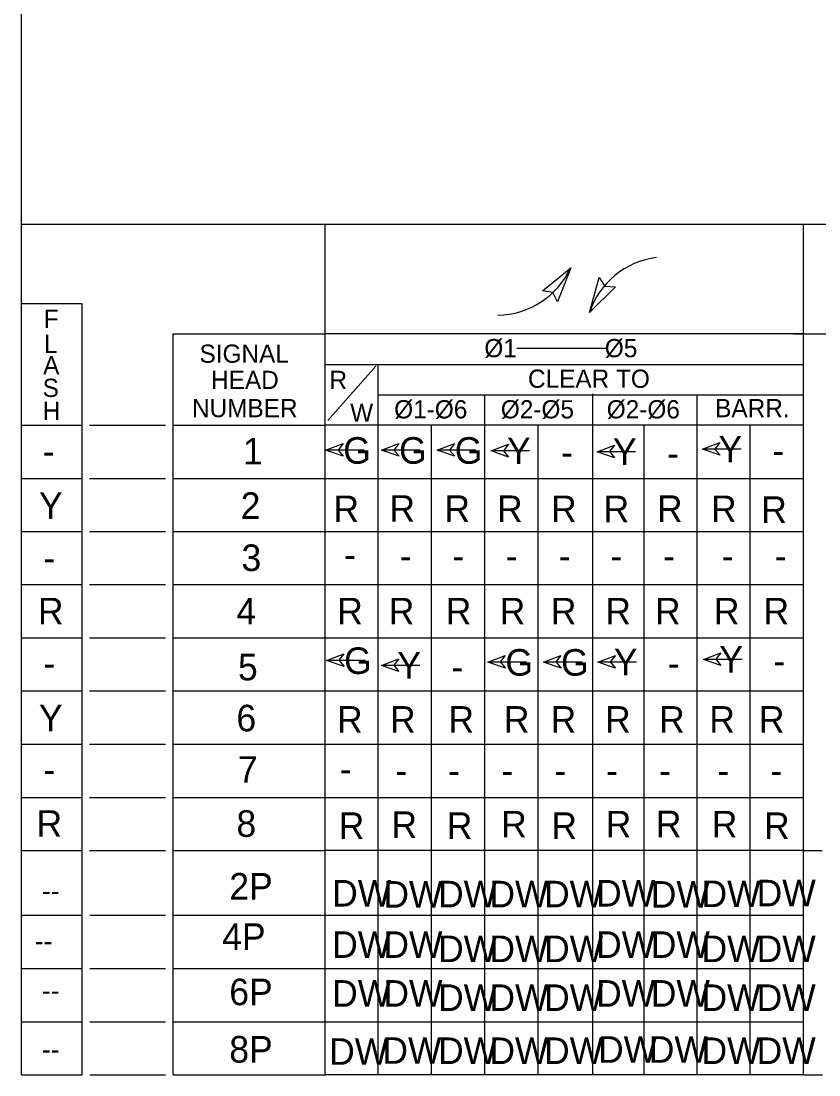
# Model space of a CAD drawing. Extents: x 0 to 3.01, y -0.05 to 1.83.
# Drawn here: x 2.2984 to 2.5103, y 1.2756 to 1.5553 of the extents above; entities that cross this region are included whole.
import ezdxf

# ---------------------------------------------------------------- set-up
doc = ezdxf.new("R2010")
doc.units = 0
for name, color, linetype in [('TR_TS_Border', 7, 'Continuous'), ('TR_TS_Phase1', 7, 'Continuous'), ('TR_TS_Phase2', 7, 'Continuous'), ('TR_TS_Phase3', 7, 'Continuous'), ('TR_TS_Phase4', 7, 'Continuous'), ('TR_TS_Phase5', 7, 'Continuous'), ('TR_TS_Phase6', 7, 'Continuous'), ('TR_TS_Phase7', 7, 'Continuous'), ('TR_TS_Phase8', 7, 'Continuous')]:
    doc.layers.add(name, color=color, linetype=linetype)

msp = doc.modelspace()

# ---------------------------------------------------------------- linework, layer by layer
at = {"layer": 'TR_TS_Border'}
for p, q in [((2.2983738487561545, 1.7049511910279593), (2.2983738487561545, 1.27559374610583)), ((2.907476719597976, 1.5013454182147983), (2.2983738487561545, 1.5013454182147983)), ((2.3790461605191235, 1.5013453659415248), (2.3790461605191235, 1.275593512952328)), ((2.506118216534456, 1.5013455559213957), (2.506118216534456, 1.27559374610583)), ((2.2983738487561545, 1.4803417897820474), (2.314508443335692, 1.4803417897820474)), ((2.314508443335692, 1.4803417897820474), (2.314508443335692, 1.27559374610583)), ((2.338710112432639, 1.4722744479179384), (2.379046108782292, 1.4722744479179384)), ((2.338710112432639, 1.4722744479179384), (2.338710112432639, 1.27559374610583)), ((2.506118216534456, 1.4722744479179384), (2.379046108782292, 1.4722744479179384)), ((2.503587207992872, 1.4722744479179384), (2.5267743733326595, 1.4722744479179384)), ((2.4300997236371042, 1.468530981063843), (2.453723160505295, 1.468530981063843)), ((2.379046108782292, 1.4642071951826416), (2.506118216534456, 1.4642071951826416)), ((2.379889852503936, 1.4492854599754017), (2.392597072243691, 1.4637328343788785)), ((2.393177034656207, 1.4642071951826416), (2.393177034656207, 1.27559374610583)), ((2.393177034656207, 1.4561402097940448), (2.506118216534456, 1.4561402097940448)), ((2.421464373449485, 1.4561402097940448), (2.421464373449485, 1.27559374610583)), ((2.450123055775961, 1.4564049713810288), (2.450123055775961, 1.275858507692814)), ((2.4779094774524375, 1.4561402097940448), (2.4779094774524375, 1.27559374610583)), ((2.2983738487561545, 1.4480727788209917), (2.314508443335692, 1.4480727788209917)), ((2.316564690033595, 1.4480727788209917), (2.3367063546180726, 1.4480727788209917)), ((2.338710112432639, 1.4480727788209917), (2.379046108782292, 1.4480727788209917)), ((2.506118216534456, 1.4480727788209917), (2.379046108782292, 1.4480727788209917)), ((2.4073335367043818, 1.4480727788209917), (2.4073335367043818, 1.27559374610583)), ((2.4355952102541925, 1.4480727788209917), (2.4355952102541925, 1.27559374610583)), ((2.4637786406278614, 1.4480727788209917), (2.4637786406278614, 1.27559374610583)), ((2.491987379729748, 1.4480727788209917), (2.491987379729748, 1.27559374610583)), ((2.2983738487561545, 1.433941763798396), (2.314508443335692, 1.433941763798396)), ((2.316564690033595, 1.433941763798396), (2.3367063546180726, 1.433941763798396)), ((2.338710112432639, 1.433941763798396), (2.506118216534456, 1.433941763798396)), ((2.2983738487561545, 1.4198639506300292), (2.314508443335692, 1.4198639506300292)), ((2.316564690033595, 1.4198639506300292), (2.3367063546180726, 1.4198639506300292)), ((2.338710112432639, 1.4198639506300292), (2.506118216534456, 1.4198639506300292)), ((2.2983738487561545, 1.405733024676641), (2.314508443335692, 1.405733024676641)), ((2.316564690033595, 1.405733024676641), (2.3367063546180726, 1.405733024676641)), ((2.338710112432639, 1.405733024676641), (2.506118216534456, 1.405733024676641)), ((2.2983738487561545, 1.3916020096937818), (2.314508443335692, 1.3916020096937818)), ((2.316564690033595, 1.3916020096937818), (2.3367063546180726, 1.3916020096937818)), ((2.338710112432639, 1.3916020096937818), (2.506118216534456, 1.3916020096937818)), ((2.2983738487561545, 1.3775241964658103), (2.314508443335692, 1.3775241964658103)), ((2.316564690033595, 1.3775241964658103), (2.3367063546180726, 1.3775241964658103)), ((2.338710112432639, 1.3775241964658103), (2.506118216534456, 1.3775241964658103)), ((2.2983738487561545, 1.3633932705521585), (2.314508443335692, 1.3633932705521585)), ((2.316564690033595, 1.3633932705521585), (2.3367063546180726, 1.3633932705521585)), ((2.338710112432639, 1.3633932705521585), (2.506118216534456, 1.3633932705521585)), ((2.2983738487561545, 1.3492622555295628), (2.314508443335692, 1.3492622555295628)), ((2.316564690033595, 1.3492622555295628), (2.3367063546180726, 1.3492622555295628)), ((2.338710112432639, 1.3492622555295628), (2.506118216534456, 1.3492622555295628)), ((2.2983738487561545, 1.3351314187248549), (2.314508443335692, 1.3351314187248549)), ((2.316564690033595, 1.3351314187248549), (2.3367063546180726, 1.3351314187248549)), ((2.338710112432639, 1.3351314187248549), (2.379046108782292, 1.3351314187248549)), ((2.506118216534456, 1.3351314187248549), (2.379046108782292, 1.3351314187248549)), ((2.506118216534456, 1.3351314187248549), (2.5111802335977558, 1.3351314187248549)), ((2.298447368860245, 1.3179863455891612), (2.314581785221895, 1.3179863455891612)), ((2.3166380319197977, 1.3179863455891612), (2.336779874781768, 1.3179863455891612)), ((2.3387833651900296, 1.3179863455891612), (2.5061917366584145, 1.3179863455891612)), ((2.298447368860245, 1.3038554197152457), (2.314581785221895, 1.3038554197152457)), ((2.3166380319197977, 1.3038554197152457), (2.336779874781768, 1.3038554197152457)), ((2.3387833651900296, 1.3038554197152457), (2.5061917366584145, 1.3038554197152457)), ((2.298447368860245, 1.2897245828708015), (2.314581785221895, 1.2897245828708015)), ((2.3166380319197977, 1.2897245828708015), (2.336779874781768, 1.2897245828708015)), ((2.3387833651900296, 1.2897245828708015), (2.5061917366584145, 1.2897245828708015)), ((2.298447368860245, 1.27559374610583), (2.314581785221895, 1.27559374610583)), ((2.3166380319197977, 1.27559374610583), (2.336779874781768, 1.27559374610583)), ((2.3387833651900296, 1.27559374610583), (2.3791196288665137, 1.27559374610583)), ((2.5061917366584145, 1.27559374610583), (2.3791196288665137, 1.27559374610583)), ((2.5061917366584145, 1.27559374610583), (2.5112536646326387, 1.27559374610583))]:
    msp.add_line(p, q, dxfattribs=at)
at = {"layer": 'TR_TS_Phase1'}
for p, q in [((2.4368316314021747, 1.4837736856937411), (2.4443714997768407, 1.4898253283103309)), ((2.4443714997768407, 1.4898253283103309), (2.440849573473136, 1.480800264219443)), ((2.4396055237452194, 1.483325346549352), (2.4368316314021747, 1.4837736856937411)), ((2.440849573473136, 1.480800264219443), (2.4396055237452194, 1.483325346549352)), ((2.3792738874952, 1.4414179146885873), (2.383908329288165, 1.443180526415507)), ((2.3895352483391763, 1.4414179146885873), (2.3792738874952, 1.4414179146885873)), ((2.383952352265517, 1.439809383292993), (2.3792738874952, 1.4414179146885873)), ((2.383908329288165, 1.443180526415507), (2.3825789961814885, 1.441476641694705)), ((2.3825789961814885, 1.441476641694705), (2.383952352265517, 1.439809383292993)), ((2.3941049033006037, 1.4414179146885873), (2.3987393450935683, 1.443180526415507)), ((2.4043663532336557, 1.4414179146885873), (2.3941049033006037, 1.4414179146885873)), ((2.398783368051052, 1.439809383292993), (2.3941049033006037, 1.4414179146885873)), ((2.3987393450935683, 1.443180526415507), (2.397410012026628, 1.441476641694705)), ((2.397410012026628, 1.441476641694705), (2.398783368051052, 1.439809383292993)), ((2.4088982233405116, 1.4414179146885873), (2.4135327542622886, 1.443180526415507)), ((2.419159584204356, 1.4414179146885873), (2.4088982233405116, 1.4414179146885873)), ((2.4135767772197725, 1.439809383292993), (2.4088982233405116, 1.4414179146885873)), ((2.4135327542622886, 1.443180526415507), (2.4122033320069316, 1.441476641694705)), ((2.4122033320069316, 1.441476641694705), (2.4135767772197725, 1.439809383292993)), ((2.4232023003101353, 1.4412230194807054), (2.42783665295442, 1.4429858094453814)), ((2.4334633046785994, 1.4412230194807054), (2.4232023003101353, 1.4412230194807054)), ((2.42788067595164, 1.4396146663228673), (2.4232023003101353, 1.4412230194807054)), ((2.42783665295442, 1.4429858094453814), (2.4265074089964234, 1.4412817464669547)), ((2.4265074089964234, 1.4412817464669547), (2.42788067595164, 1.4396146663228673)), ((2.451358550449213, 1.4409954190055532), (2.4559929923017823, 1.442758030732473)), ((2.4616196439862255, 1.4409954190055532), (2.451358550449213, 1.4409954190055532)), ((2.45603701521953, 1.439386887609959), (2.451358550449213, 1.4409954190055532)), ((2.4559929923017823, 1.442758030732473), (2.4546636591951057, 1.4410542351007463)), ((2.4546636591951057, 1.4410542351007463), (2.45603701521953, 1.439386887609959)), ((2.4793790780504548, 1.441678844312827), (2.4840134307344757, 1.443441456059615)), ((2.4896400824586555, 1.441678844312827), (2.4793790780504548, 1.441678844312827)), ((2.4840574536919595, 1.4400703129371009), (2.4793790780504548, 1.441678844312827)), ((2.4840134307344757, 1.443441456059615), (2.482684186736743, 1.441737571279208)), ((2.482684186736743, 1.441737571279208), (2.4840574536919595, 1.4400703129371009))]:
    msp.add_line(p, q, dxfattribs=at)
msp.add_arc((2.4246866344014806, 1.4988934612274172), 0.02161745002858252, 270.9422666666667, 335.3874333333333, dxfattribs=at)
at = {"layer": 'TR_TS_Phase5'}
for p, q in [((2.4493976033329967, 1.4779521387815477), (2.4519162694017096, 1.4873070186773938)), ((2.4519162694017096, 1.4873070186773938), (2.4534273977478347, 1.4849325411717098)), ((2.4562339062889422, 1.4847884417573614), (2.4493976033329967, 1.4779521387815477)), ((2.4534273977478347, 1.4849325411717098), (2.4562339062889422, 1.4847884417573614)), ((2.4796064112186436, 1.3858729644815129), (2.48424085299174, 1.387635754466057)), ((2.48424085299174, 1.387635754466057), (2.4829115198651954, 1.3859316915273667)), ((2.3795012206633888, 1.3856120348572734), (2.384135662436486, 1.3873748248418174)), ((2.3897626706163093, 1.3856120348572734), (2.3795012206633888, 1.3856120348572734)), ((2.384179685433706, 1.3840036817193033), (2.3795012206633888, 1.3856120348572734)), ((2.384135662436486, 1.3873748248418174), (2.3828063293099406, 1.3856707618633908)), ((2.3828063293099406, 1.3856707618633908), (2.384179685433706, 1.3840036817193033)), ((2.3940705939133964, 1.3842786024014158), (2.3987050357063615, 1.3860412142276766)), ((2.3987050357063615, 1.3860412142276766), (2.3973757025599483, 1.3843374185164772)), ((2.4223260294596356, 1.3851563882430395), (2.426960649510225, 1.386919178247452)), ((2.4325874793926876, 1.3851563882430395), (2.4223260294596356, 1.3851563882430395)), ((2.427004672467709, 1.3835478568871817), (2.4223260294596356, 1.3851563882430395)), ((2.426960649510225, 1.386919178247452), (2.4256311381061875, 1.3852151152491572)), ((2.4256311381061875, 1.3852151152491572), (2.427004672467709, 1.3835478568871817)), ((2.437119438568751, 1.3851563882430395), (2.4417540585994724, 1.386919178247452)), ((2.4473808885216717, 1.3851563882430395), (2.437119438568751, 1.3851563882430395)), ((2.441798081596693, 1.3835478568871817), (2.437119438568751, 1.3851563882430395)), ((2.4417540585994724, 1.386919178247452), (2.440424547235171, 1.3852151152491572)), ((2.440424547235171, 1.3852151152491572), (2.441798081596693, 1.3835478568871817)), ((2.4515859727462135, 1.385189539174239), (2.4562204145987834, 1.3869523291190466)), ((2.461847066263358, 1.385189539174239), (2.4515859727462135, 1.385189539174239)), ((2.4562644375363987, 1.3835810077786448), (2.4515859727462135, 1.385189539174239)), ((2.4562204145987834, 1.3869523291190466), (2.4548910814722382, 1.3852483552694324)), ((2.4548910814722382, 1.3852483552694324), (2.4562644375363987, 1.3835810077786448)), ((2.489867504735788, 1.3858729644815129), (2.4796064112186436, 1.3858729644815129)), ((2.4842848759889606, 1.3842644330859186), (2.4796064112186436, 1.3858729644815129)), ((2.4829115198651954, 1.3859316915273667), (2.4842848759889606, 1.3842644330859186)), ((2.4043316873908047, 1.3842786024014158), (2.3940705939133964, 1.3842786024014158)), ((2.3987490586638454, 1.382670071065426), (2.3940705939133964, 1.3842786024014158)), ((2.3973757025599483, 1.3843374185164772), (2.3987490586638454, 1.382670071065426))]:
    msp.add_line(p, q, dxfattribs=at)
msp.add_arc((2.4698457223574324, 1.4711175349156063), 0.021617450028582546, 97.19140000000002, 161.63656666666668, dxfattribs=at)

# ---------------------------------------------------------------- texts
at = {"layer": 'TR_TS_Border'}
for s, height, p in [('F', 0.004840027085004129, (2.304359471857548, 1.473908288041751)), ('L', 0.004840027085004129, (2.3044841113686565, 1.4672645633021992)), ('SIGNAL', 0.004840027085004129, (2.345774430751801, 1.464628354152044)), ('Ø1             Ø5', 0.004840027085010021, (2.4214208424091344, 1.466104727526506)), ('A', 0.004840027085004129, (2.30423977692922, 1.46157000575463)), ('S', 0.004840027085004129, (2.3040989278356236, 1.4555591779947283)), ('HEAD', 0.004840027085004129, (2.34884864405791, 1.457668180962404)), ('R', 0.004840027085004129, (2.38029688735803, 1.457668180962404)), ('CLEAR TO', 0.004840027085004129, (2.4330146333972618, 1.4579846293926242)), ('NUMBER', 0.004840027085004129, (2.3437718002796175, 1.4501810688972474)), ('Ø1-Ø6', 0.004840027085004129, (2.397485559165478, 1.4498646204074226)), ('Ø2-Ø5', 0.004840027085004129, (2.4258108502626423, 1.4498646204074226)), ('Ø2-Ø6', 0.004840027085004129, (2.4539413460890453, 1.4498646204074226)), ('BARR.', 0.004840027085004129, (2.4827323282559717, 1.4501810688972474)), ('H', 0.004840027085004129, (2.304124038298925, 1.4494428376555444)), ('W', 0.004840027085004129, (2.3857909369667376, 1.4489682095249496))]:
    msp.add_text(s, height=height, rotation=360, dxfattribs=at).set_placement(p)
at = {"layer": 'TR_TS_Phase1'}
for s, p in [('1', (2.357327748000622, 1.4376521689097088)), ('G', (2.383950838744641, 1.4378358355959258)), ('G', (2.3987823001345, 1.4378358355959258)), ('G', (2.4135757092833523, 1.4378358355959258)), ('Y', (2.427431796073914, 1.4377340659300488)), ('Y', (2.455588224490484, 1.4375065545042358)), ('Y', (2.483608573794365, 1.4381895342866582)), ('-', (2.304098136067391, 1.4376521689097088)), ('-', (2.4979788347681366, 1.4378358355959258)), ('-', (2.441802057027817, 1.4373803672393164)), ('-', (2.469958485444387, 1.4371528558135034))]:
    msp.add_text(s, height=0.007050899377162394, dxfattribs=at).set_placement(p)
at = {"layer": 'TR_TS_Phase2'}
for s, p in [('Y', (2.3031285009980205, 1.4231914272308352)), ('2', (2.3567041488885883, 1.4231914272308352))]:
    msp.add_text(s, height=0.007050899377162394, rotation=360, dxfattribs=at).set_placement(p)
for s, height, p in [('R', 0.007050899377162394, (2.381339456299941, 1.4223307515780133)), ('R', 0.007050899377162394, (2.3962089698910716, 1.4224151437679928)), ('R', 0.007050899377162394, (2.4108127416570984, 1.422395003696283)), ('R', 0.007050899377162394, (2.424800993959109, 1.4223560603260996)), ('R', 0.007050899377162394, (2.4391517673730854, 1.4223357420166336)), ('R', 0.007050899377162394, (2.4530972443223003, 1.4223218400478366)), ('R', 0.007050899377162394, (2.4672795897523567, 1.4223858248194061)), ('R', 0.007050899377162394, (2.481631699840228, 1.4223307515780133)), ('R', 0.007050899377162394, (2.4949716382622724, 1.4221420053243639)), ('2P', 0.007050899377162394, (2.3536810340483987, 1.3221382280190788)), ('DW', 0.007050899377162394, (2.3809983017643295, 1.3202967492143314)), ('DW', 0.007050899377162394, (2.394601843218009, 1.319995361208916)), ('DW', 0.007050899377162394, (2.409129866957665, 1.3200736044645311)), ('DW', 0.007050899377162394, (2.4227592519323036, 1.3200736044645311)), ('DW', 0.007050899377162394, (2.4372873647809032, 1.3200736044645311)), ('DW', 0.007050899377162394, (2.45109845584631, 1.3202967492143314)), ('DW', 0.007050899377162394, (2.4656265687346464, 1.319995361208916)), ('DW', 0.007050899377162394, (2.47910009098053, 1.320149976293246)), ('DW', 0.007050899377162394, (2.493741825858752, 1.3203438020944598)), ('--', 0.005251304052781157, (2.303913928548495, 1.321869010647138))]:
    msp.add_text(s, height=height, dxfattribs=at).set_placement(p)
at = {"layer": 'TR_TS_Phase3'}
for s, p in [('3', (2.356925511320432, 1.4093552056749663)), ('-', (2.384202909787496, 1.4102400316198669)), ('-', (2.39892440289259, 1.4098391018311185)), ('-', (2.4129585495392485, 1.4098391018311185)), ('-', (2.4271453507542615, 1.4098391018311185)), ('-', (2.441179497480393, 1.4098391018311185)), ('-', (2.4549020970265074, 1.4098391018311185)), ('-', (2.468936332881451, 1.4098391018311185)), ('-', (2.4845156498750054, 1.4098391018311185)), ('-', (2.498549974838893, 1.4098391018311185)), ('-', (2.304339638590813, 1.4093552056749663))]:
    msp.add_text(s, height=0.007050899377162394, dxfattribs=at).set_placement(p)
at = {"layer": 'TR_TS_Phase4'}
for s, p in [('R', (2.3028569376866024, 1.3951837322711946)), ('4', (2.355584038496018, 1.3951837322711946)), ('R', (2.382351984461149, 1.3951837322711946)), ('R', (2.396048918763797, 1.3951837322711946)), ('R', (2.4111725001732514, 1.3951837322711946)), ('R', (2.425520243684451, 1.3951837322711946)), ('R', (2.4390925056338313, 1.3951837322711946)), ('R', (2.45355850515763, 1.3951837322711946)), ('R', (2.466743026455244, 1.3951837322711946)), ('R', (2.4823992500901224, 1.3951837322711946)), ('R', (2.495583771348, 1.3951837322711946))]:
    msp.add_text(s, height=0.007050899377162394, rotation=360, dxfattribs=at).set_placement(p)
for s, height, p in [('4P', 0.007050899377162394, (2.351796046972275, 1.3087870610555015)), ('DW', 0.007050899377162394, (2.3809983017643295, 1.3066650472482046)), ('DW', 0.007050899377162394, (2.394601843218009, 1.3066650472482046)), ('DW', 0.007050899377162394, (2.409129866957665, 1.305538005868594)), ('DW', 0.007050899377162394, (2.4227592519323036, 1.305538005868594)), ('DW', 0.007050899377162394, (2.4372873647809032, 1.305538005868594)), ('DW', 0.007050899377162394, (2.45109845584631, 1.3066650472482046)), ('DW', 0.007050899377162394, (2.4656265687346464, 1.3066650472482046)), ('DW', 0.007050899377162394, (2.47910009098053, 1.305538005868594)), ('DW', 0.007050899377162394, (2.493741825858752, 1.305538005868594)), ('--', 0.005251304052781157, (2.3020291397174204, 1.308518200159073))]:
    msp.add_text(s, height=height, dxfattribs=at).set_placement(p)
at = {"layer": 'TR_TS_Phase5'}
for s, p in [('G', (2.3841782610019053, 1.3820303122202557)), ('Y', (2.3983002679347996, 1.380789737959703)), ('G', (2.4270032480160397, 1.3815746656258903)), ('G', (2.441796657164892, 1.3815746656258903)), ('Y', (2.4558155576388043, 1.3817006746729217)), ('Y', (2.4838359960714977, 1.3823840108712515)), ('5', (2.3559931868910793, 1.3803307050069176)), ('-', (2.498206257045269, 1.3820303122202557)), ('-', (2.3043232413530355, 1.381356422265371)), ('-', (2.412670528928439, 1.3804360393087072)), ('-', (2.470185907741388, 1.3813469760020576))]:
    msp.add_text(s, height=0.007050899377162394, dxfattribs=at).set_placement(p)
at = {"layer": 'TR_TS_Phase6'}
for s, p in [('Y', (2.3031285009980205, 1.3668027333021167)), ('6', (2.355583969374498, 1.3668027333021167))]:
    msp.add_text(s, height=0.007050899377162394, rotation=360, dxfattribs=at).set_placement(p)
for s, height, p in [('R', 0.007050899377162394, (2.382288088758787, 1.3664307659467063)), ('R', 0.007050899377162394, (2.396372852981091, 1.3664307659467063)), ('R', 0.007050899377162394, (2.4118841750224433, 1.3664307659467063)), ('R', 0.007050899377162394, (2.426619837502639, 1.3664307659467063)), ('R', 0.007050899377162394, (2.439028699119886, 1.3664307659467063)), ('R', 0.007050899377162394, (2.4534946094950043, 1.3664307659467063)), ('R', 0.007050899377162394, (2.467842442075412, 1.3664307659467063)), ('R', 0.007050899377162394, (2.481171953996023, 1.3664307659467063)), ('R', 0.007050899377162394, (2.4943566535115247, 1.3664307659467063)), ('6P', 0.007050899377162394, (2.3536810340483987, 1.2941032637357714)), ('DW', 0.007050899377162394, (2.3809983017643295, 1.293702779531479)), ('DW', 0.007050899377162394, (2.394601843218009, 1.293702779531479)), ('DW', 0.007050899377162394, (2.409129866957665, 1.2925754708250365)), ('DW', 0.007050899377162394, (2.4227592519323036, 1.2925754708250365)), ('DW', 0.007050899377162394, (2.4372873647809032, 1.2925754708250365)), ('DW', 0.007050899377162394, (2.45109845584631, 1.293702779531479)), ('DW', 0.007050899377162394, (2.4656265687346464, 1.293702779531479)), ('DW', 0.007050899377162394, (2.47910009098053, 1.2925754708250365)), ('DW', 0.007050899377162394, (2.493741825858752, 1.2925754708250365)), ('--', 0.005251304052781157, (2.303913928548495, 1.295392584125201))]:
    msp.add_text(s, height=height, dxfattribs=at).set_placement(p)
at = {"layer": 'TR_TS_Phase7'}
for s, p in [('7', (2.3559931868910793, 1.3531551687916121)), ('-', (2.3043232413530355, 1.3531551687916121)), ('-', (2.383064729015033, 1.3532955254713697)), ('-', (2.3977862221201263, 1.3528945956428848)), ('-', (2.411820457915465, 1.3528945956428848)), ('-', (2.426007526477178, 1.3528945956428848)), ('-', (2.440041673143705, 1.3528945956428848)), ('-', (2.453763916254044, 1.3528945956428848)), ('-', (2.4677983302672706, 1.3528945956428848)), ('-', (2.4833776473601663, 1.3528945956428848)), ('-', (2.4974117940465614, 1.3528945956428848))]:
    msp.add_text(s, height=0.007050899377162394, dxfattribs=at).set_placement(p)
at = {"layer": 'TR_TS_Phase8'}
for s, p in [('R', (2.302483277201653, 1.338795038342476)), ('8', (2.355583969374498, 1.338795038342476))]:
    msp.add_text(s, height=0.007050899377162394, rotation=360, dxfattribs=at).set_placement(p)
for s, height, p in [('R', 0.007050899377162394, (2.4258923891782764, 1.3386411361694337)), ('R', 0.007050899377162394, (2.45364922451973, 1.3386411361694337)), ('R', 0.007050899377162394, (2.466979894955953, 1.3386951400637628)), ('R', 0.007050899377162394, (2.4818414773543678, 1.3386411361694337)), ('R', 0.007050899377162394, (2.3827431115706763, 1.3382398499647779)), ('R', 0.007050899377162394, (2.396760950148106, 1.3384936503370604)), ('R', 0.007050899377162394, (2.411457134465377, 1.3382398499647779)), ('R', 0.007050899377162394, (2.4392228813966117, 1.3382398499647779)), ('R', 0.007050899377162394, (2.495724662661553, 1.3382122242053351)), ('8P', 0.007050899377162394, (2.3536810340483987, 1.2788660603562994)), ('DW', 0.007050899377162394, (2.380199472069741, 1.2782810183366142)), ('DW', 0.007050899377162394, (2.3943354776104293, 1.2785473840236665)), ('DW', 0.007050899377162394, (2.409129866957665, 1.2784857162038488)), ('DW', 0.007050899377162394, (2.4227592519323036, 1.2784857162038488)), ('DW', 0.007050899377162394, (2.4372873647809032, 1.2784857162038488)), ('DW', 0.007050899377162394, (2.4516310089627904, 1.2788139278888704)), ('DW', 0.007050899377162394, (2.4650939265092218, 1.2788139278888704)), ('DW', 0.007050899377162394, (2.47910009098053, 1.2784857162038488)), ('DW', 0.007050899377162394, (2.493741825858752, 1.2784857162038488)), ('--', 0.005251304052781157, (2.303913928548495, 1.279765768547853))]:
    msp.add_text(s, height=height, dxfattribs=at).set_placement(p)

doc.saveas('drawing.dxf')
